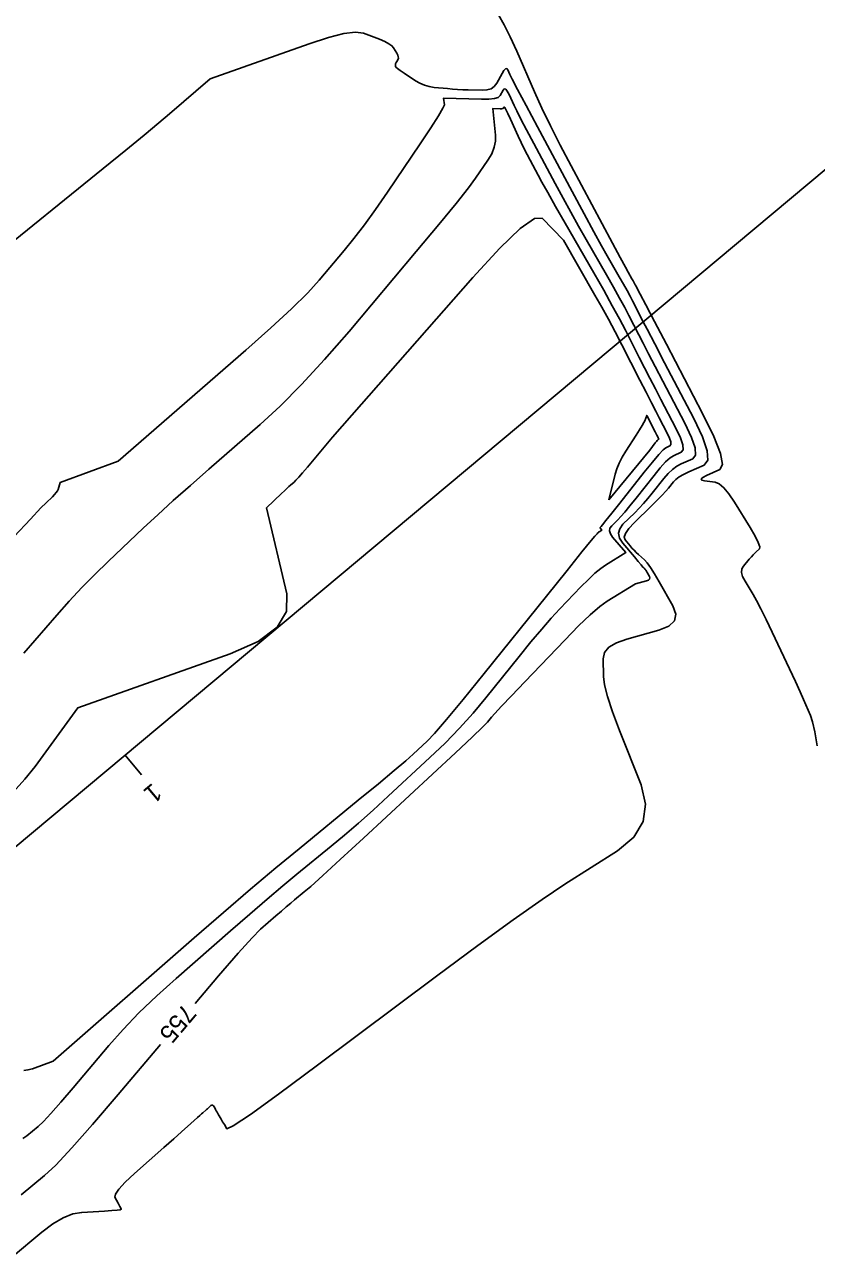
# Model space of a CAD drawing. Extents: x 2082232 to 2083549, y 592624 to 593832.
# Drawn here: x 2082789.01 to 2082819.92, y 593291.52 to 593339.64 of the extents above; entities that cross this region are included whole.
import ezdxf

# ---------------------------------------------------------------- set-up
doc = ezdxf.new("R2010")
doc.units = 0
for name, color, linetype in [('DT_X_Contour_Major', 7, 'Continuous'), ('DT_X_Contour_Minor', 7, 'Continuous'), ('GE_P_CL_5', 7, 'Continuous')]:
    doc.layers.add(name, color=color, linetype=linetype)

msp = doc.modelspace()

# ---------------------------------------------------------------- linework, layer by layer
at = {"layer": 'DT_X_Contour_Major'}
for points in [[(2082813.96, 593321.919), (2082814.129, 593322.115), (2082814.299, 593322.277), (2082814.468, 593322.404), (2082814.638, 593322.496), (2082815.089, 593322.696), (2082815.197, 593322.838), (2082815.182, 593323.117), (2082815.044, 593323.53), (2082814.782, 593324.08), (2082813.922, 593325.725), (2082813.621, 593326.301), (2082813.365, 593326.793), (2082813.154, 593327.201), (2082812.987, 593327.526), (2082812.602, 593328.282), (2082812.439, 593328.594), (2082812.238, 593328.964), (2082811.999, 593329.392), (2082811.722, 593329.878), (2082810.934, 593331.25), (2082810.636, 593331.773), (2082810.334, 593332.313), (2082810.028, 593332.87), (2082809.719, 593333.444), (2082808.887, 593334.997), (2082808.605, 593335.527), (2082808.383, 593335.952), (2082808.22, 593336.271), (2082808.117, 593336.485), (2082807.921, 593336.914), (2082807.851, 593337.046), (2082807.789, 593337.117), (2082807.735, 593337.127), (2082807.688, 593337.078), (2082807.572, 593336.867), (2082807.494, 593336.798), (2082807.348, 593336.752), (2082807.133, 593336.728), (2082806.85, 593336.726), (2082805.367, 593336.769), (2082805.395, 593336.512), (2082805.34, 593336.375), (2082805.165, 593336.075), (2082804.868, 593335.613), (2082804.45, 593334.987), (2082803.174, 593333.1), (2082802.71, 593332.427), (2082802.274, 593331.822), (2082801.866, 593331.285), (2082801.486, 593330.817), (2082800.512, 593329.66), (2082800.059, 593329.164), (2082799.43, 593328.545), (2082798.625, 593327.802), (2082797.645, 593326.935), (2082792.659, 593322.602), (2082790.395, 593321.764), (2082790.313, 593321.5), (2082790.287, 593321.439), (2082790.241, 593321.371), (2082790.176, 593321.295), (2082790.092, 593321.212), (2082789.843, 593320.979), (2082789.643, 593320.774), (2082789.23, 593320.332), (2082788.604, 593319.653)], [(2082795.662, 593301.437), (2082796.571, 593302.506), (2082797.339, 593303.39), (2082797.889, 593303.999), (2082798.222, 593304.332), (2082798.817, 593304.852), (2082799.03, 593305.038), (2082799.222, 593305.203), (2082799.395, 593305.349), (2082799.547, 593305.475), (2082799.926, 593305.785), (2082800.177, 593306.003), (2082800.645, 593306.427), (2082801.331, 593307.056), (2082802.234, 593307.891), (2082804.933, 593310.389), (2082805.827, 593311.218), (2082806.482, 593311.832), (2082806.899, 593312.23), (2082807.078, 593312.413), (2082807.239, 593312.613), (2082807.365, 593312.755), (2082807.623, 593313.031), (2082808.012, 593313.441), (2082808.532, 593313.985), (2082810.095, 593315.614), (2082810.637, 593316.167), (2082811.093, 593316.604), (2082811.463, 593316.925), (2082811.745, 593317.13), (2082812.863, 593317.815), (2082813.288, 593317.931), (2082813.363, 593317.96), (2082813.408, 593317.998), (2082813.421, 593318.043), (2082813.404, 593318.097), (2082813.316, 593318.252), (2082813.285, 593318.304), (2082813.259, 593318.345), (2082813.237, 593318.376), (2082813.22, 593318.394), (2082813.18, 593318.43), (2082813.146, 593318.467), (2082813.073, 593318.551), (2082812.962, 593318.682), (2082812.813, 593318.86), (2082812.362, 593319.397), (2082812.236, 593319.594), (2082812.195, 593319.783), (2082812.239, 593319.964), (2082812.368, 593320.137), (2082812.826, 593320.587), (2082812.997, 593320.761), (2082813.168, 593320.946), (2082813.339, 593321.143), (2082813.508, 593321.35), (2082813.96, 593321.919)], [(2082788.873, 593293.961), (2082789.786, 593294.718), (2082790.222, 593295.128), (2082790.847, 593295.793), (2082791.66, 593296.711), (2082792.662, 593297.882), (2082794.307, 593299.832)]]:
    msp.add_lwpolyline(points, dxfattribs=at)
at = {"layer": 'DT_X_Contour_Minor'}
for points in [[(2082807.513, 593340.023), (2082807.731, 593339.633), (2082807.966, 593339.16), (2082808.218, 593338.605), (2082808.914, 593337.012), (2082809.2, 593336.384), (2082809.533, 593335.693), (2082809.914, 593334.939), (2082810.344, 593334.123), (2082811.553, 593331.863), (2082811.957, 593331.11), (2082812.261, 593330.544), (2082812.465, 593330.167), (2082812.57, 593329.978), (2082812.716, 593329.723), (2082812.767, 593329.634), (2082812.811, 593329.554), (2082812.849, 593329.486), (2082812.879, 593329.428), (2082812.95, 593329.288), (2082813.04, 593329.116), (2082813.255, 593328.703), (2082813.596, 593328.052), (2082814.062, 593327.16), (2082815.473, 593324.463), (2082815.912, 593323.567), (2082816.17, 593322.903), (2082816.249, 593322.471), (2082816.146, 593322.27), (2082815.633, 593322.043), (2082815.484, 593321.966), (2082815.421, 593321.905), (2082815.445, 593321.861), (2082815.554, 593321.833), (2082815.962, 593321.779), (2082816.125, 593321.715), (2082816.306, 593321.564), (2082816.506, 593321.324), (2082816.724, 593320.997), (2082817.331, 593320.008), (2082817.525, 593319.677), (2082817.65, 593319.429), (2082817.706, 593319.262), (2082817.693, 593319.176), (2082817.568, 593319.057), (2082817.517, 593319.006), (2082817.455, 593318.94), (2082817.383, 593318.862), (2082817.301, 593318.769), (2082817.069, 593318.505), (2082817.007, 593318.394), (2082816.998, 593318.259), (2082817.039, 593318.099), (2082817.133, 593317.915), (2082817.45, 593317.393), (2082817.586, 593317.155), (2082817.755, 593316.83), (2082817.957, 593316.42), (2082818.193, 593315.925), (2082818.867, 593314.489), (2082819.097, 593313.998), (2082819.281, 593313.601), (2082819.419, 593313.3), (2082819.511, 593313.093), (2082819.695, 593312.667), (2082819.769, 593312.43), (2082819.854, 593312.037), (2082819.949, 593311.49)], [(2082787.595, 593330.408), (2082792.071, 593334.021), (2082792.952, 593334.735), (2082793.678, 593335.328), (2082794.25, 593335.802), (2082794.666, 593336.154), (2082796.245, 593337.519), (2082800.114, 593338.893), (2082800.869, 593339.14), (2082801.474, 593339.291), (2082801.93, 593339.345), (2082802.237, 593339.305), (2082802.856, 593339.068), (2082803.065, 593338.98), (2082803.227, 593338.895), (2082803.344, 593338.812), (2082803.413, 593338.732), (2082803.537, 593338.52), (2082803.575, 593338.447), (2082803.597, 593338.384), (2082803.601, 593338.332), (2082803.588, 593338.291), (2082803.533, 593338.197), (2082803.514, 593338.163), (2082803.5, 593338.132), (2082803.492, 593338.104), (2082803.488, 593338.079), (2082803.485, 593338.016), (2082803.505, 593337.981), (2082803.567, 593337.925), (2082803.672, 593337.846), (2082803.82, 593337.746), (2082804.269, 593337.449), (2082804.441, 593337.35), (2082804.619, 593337.273), (2082804.804, 593337.22), (2082804.996, 593337.19), (2082805.516, 593337.14), (2082805.712, 593337.123), (2082805.912, 593337.11), (2082806.114, 593337.099), (2082806.318, 593337.091), (2082806.868, 593337.076), (2082807.058, 593337.088), (2082807.216, 593337.138), (2082807.342, 593337.226), (2082807.437, 593337.35), (2082807.645, 593337.733), (2082807.718, 593337.849), (2082807.779, 593337.912), (2082807.829, 593337.921), (2082807.867, 593337.877), (2082807.953, 593337.687), (2082808.045, 593337.506), (2082808.255, 593337.106), (2082808.585, 593336.487), (2082809.033, 593335.648), (2082810.386, 593333.12), (2082810.852, 593332.252), (2082811.235, 593331.545), (2082811.535, 593330.999), (2082811.752, 593330.614), (2082812.219, 593329.801), (2082812.383, 593329.513), (2082812.525, 593329.259), (2082812.644, 593329.04), (2082812.741, 593328.855), (2082812.969, 593328.407), (2082813.097, 593328.158), (2082813.31, 593327.748), (2082813.608, 593327.176), (2082813.992, 593326.443), (2082815.128, 593324.271), (2082815.473, 593323.546), (2082815.655, 593323), (2082815.675, 593322.633), (2082815.533, 593322.445), (2082814.937, 593322.181), (2082814.732, 593322.083), (2082814.564, 593321.986), (2082814.433, 593321.89), (2082814.339, 593321.795), (2082814.139, 593321.543), (2082814.042, 593321.429), (2082813.9, 593321.277), (2082813.714, 593321.086), (2082813.484, 593320.857), (2082812.81, 593320.195), (2082812.598, 593319.967), (2082812.467, 593319.78), (2082812.418, 593319.632), (2082812.45, 593319.525), (2082812.645, 593319.293), (2082812.72, 593319.207), (2082812.799, 593319.122), (2082812.882, 593319.039), (2082812.97, 593318.958), (2082813.209, 593318.744), (2082813.312, 593318.63), (2082813.443, 593318.449), (2082813.6, 593318.2), (2082813.785, 593317.885), (2082814.314, 593316.954), (2082814.429, 593316.633), (2082814.377, 593316.366), (2082814.158, 593316.155), (2082813.772, 593316), (2082812.522, 593315.658), (2082812.112, 593315.513), (2082811.82, 593315.336), (2082811.647, 593315.126), (2082811.592, 593314.884), (2082811.602, 593314.194), (2082811.645, 593313.868), (2082811.765, 593313.408), (2082811.962, 593312.814), (2082812.237, 593312.087), (2082813.072, 593309.968), (2082813.25, 593309.211), (2082813.157, 593308.53), (2082812.792, 593307.925), (2082812.157, 593307.395), (2082810.102, 593306.083), (2082809.21, 593305.49), (2082808.076, 593304.695), (2082806.7, 593303.696), (2082805.082, 593302.496), (2082800.446, 593299.024), (2082798.92, 593297.892), (2082797.82, 593297.101), (2082797.146, 593296.651), (2082796.898, 593296.541), (2082796.804, 593296.703), (2082796.737, 593296.818), (2082796.706, 593296.871), (2082796.678, 593296.92), (2082796.604, 593297.048), (2082796.578, 593297.092), (2082796.538, 593297.162), (2082796.523, 593297.188), (2082796.489, 593297.247), (2082796.475, 593297.27), (2082796.46, 593297.295), (2082796.427, 593297.353), (2082796.379, 593297.436), (2082796.359, 593297.46), (2082796.337, 593297.469), (2082796.311, 593297.464), (2082796.282, 593297.445), (2082796.202, 593297.373), (2082796.171, 593297.346), (2082796.142, 593297.32), (2082796.113, 593297.294), (2082796.084, 593297.269), (2082795.97, 593297.168), (2082795.916, 593297.119), (2082795.843, 593297.055), (2082795.754, 593296.976), (2082795.491, 593296.743), (2082795.13, 593296.422), (2082794.826, 593296.152), (2082794.44, 593295.81), (2082793.3, 593294.799), (2082792.931, 593294.456), (2082792.681, 593294.187), (2082792.549, 593293.991), (2082792.535, 593293.868), (2082792.654, 593293.638), (2082792.694, 593293.561), (2082792.725, 593293.502), (2082792.758, 593293.437), (2082792.778, 593293.398), (2082792.743, 593293.383), (2082792.623, 593293.367), (2082792.417, 593293.35), (2082792.126, 593293.331), (2082791.236, 593293.279), (2082790.888, 593293.216), (2082790.513, 593293.066), (2082790.111, 593292.829), (2082789.681, 593292.505), (2082788.497, 593291.524)], [(2082813.581, 593322.044), (2082813.826, 593322.341), (2082814.034, 593322.568), (2082814.205, 593322.724), (2082814.339, 593322.81), (2082814.646, 593322.946), (2082814.719, 593323.043), (2082814.709, 593323.233), (2082814.615, 593323.514), (2082814.437, 593323.888), (2082813.851, 593325.008), (2082813.634, 593325.425), (2082813.42, 593325.837), (2082813.211, 593326.244), (2082813.006, 593326.646), (2082812.464, 593327.709), (2082812.234, 593328.149), (2082811.951, 593328.669), (2082811.615, 593329.271), (2082811.225, 593329.955), (2082810.116, 593331.886), (2082809.737, 593332.546), (2082809.433, 593333.08), (2082809.205, 593333.487), (2082809.051, 593333.768), (2082808.741, 593334.346), (2082808.625, 593334.568), (2082808.51, 593334.797), (2082808.395, 593335.036), (2082808.28, 593335.282), (2082807.975, 593335.952), (2082807.874, 593336.17), (2082807.799, 593336.321), (2082807.751, 593336.406), (2082807.73, 593336.424), (2082807.708, 593336.383), (2082807.693, 593336.37), (2082807.664, 593336.361), (2082807.623, 593336.356), (2082807.568, 593336.356), (2082807.283, 593336.364), (2082807.396, 593335.318), (2082807.395, 593335.089), (2082807.344, 593334.85), (2082807.242, 593334.601), (2082807.089, 593334.342), (2082806.613, 593333.64), (2082806.335, 593333.263), (2082805.855, 593332.661), (2082805.174, 593331.833), (2082804.292, 593330.779), (2082801.672, 593327.666), (2082800.718, 593326.564), (2082799.822, 593325.589), (2082798.984, 593324.744), (2082798.204, 593324.026), (2082796.199, 593322.285), (2082795.477, 593321.652), (2082794.811, 593321.059), (2082794.203, 593320.506), (2082793.653, 593319.993), (2082792.262, 593318.679), (2082791.746, 593318.179), (2082791.24, 593317.663), (2082790.744, 593317.131), (2082790.258, 593316.584), (2082788.977, 593315.104)], [(2082813.201, 593322.168), (2082813.522, 593322.566), (2082813.769, 593322.858), (2082813.941, 593323.044), (2082814.04, 593323.125), (2082814.203, 593323.197), (2082814.242, 593323.248), (2082814.236, 593323.349), (2082814.186, 593323.498), (2082814.092, 593323.696), (2082813.781, 593324.291), (2082813.646, 593324.55), (2082813.475, 593324.882), (2082813.268, 593325.287), (2082813.024, 593325.765), (2082812.326, 593327.136), (2082812.063, 593327.644), (2082811.801, 593328.137), (2082811.537, 593328.617), (2082811.274, 593329.084), (2082810.041, 593331.227), (2082809.214, 593332.08), (2082808.912, 593332.073), (2082808.36, 593331.686), (2082807.559, 593330.918), (2082806.509, 593329.771), (2082801.028, 593323.531), (2082800.05, 593322.37), (2082799.861, 593322.147), (2082799.71, 593321.974), (2082799.599, 593321.852), (2082799.527, 593321.782), (2082799.388, 593321.661), (2082799.327, 593321.606), (2082799.247, 593321.534), (2082799.149, 593321.443), (2082799.034, 593321.334), (2082798.451, 593320.783), (2082799.246, 593317.422), (2082799.235, 593316.736), (2082798.863, 593316.117), (2082798.13, 593315.565), (2082797.035, 593315.08), (2082791.08, 593312.976), (2082789.415, 593310.676), (2082789.021, 593310.182), (2082788.555, 593309.685)], [(2082811.82, 593321.086), (2082812.064, 593322.086), (2082812.128, 593322.303), (2082812.218, 593322.526), (2082812.334, 593322.753), (2082812.474, 593322.986), (2082812.883, 593323.613), (2082813.019, 593323.825), (2082813.121, 593323.989), (2082813.188, 593324.105), (2082813.221, 593324.174), (2082813.297, 593324.385), (2082813.62, 593323.75), (2082813.662, 593323.669), (2082813.692, 593323.61), (2082813.711, 593323.573), (2082813.747, 593323.505), (2082813.758, 593323.482), (2082813.763, 593323.465), (2082813.764, 593323.453), (2082813.759, 593323.447), (2082813.741, 593323.439), (2082813.729, 593323.429), (2082813.706, 593323.404), (2082813.674, 593323.366), (2082813.631, 593323.313), (2082813.41, 593323.033), (2082811.82, 593321.086)], [(2082788.933, 593296.16), (2082789.095, 593296.271), (2082789.53, 593296.631), (2082789.738, 593296.827), (2082790.036, 593297.143), (2082790.423, 593297.581), (2082790.9, 593298.139), (2082792.293, 593299.789), (2082792.848, 593300.417), (2082793.472, 593301.064), (2082794.164, 593301.729), (2082794.923, 593302.413), (2082797.038, 593304.262), (2082797.795, 593304.92), (2082798.48, 593305.508), (2082799.093, 593306.026), (2082799.634, 593306.474), (2082800.98, 593307.575), (2082801.498, 593308.006), (2082802.042, 593308.476), (2082802.611, 593308.982), (2082803.206, 593309.526), (2082804.828, 593311.027), (2082805.421, 593311.596), (2082805.983, 593312.174), (2082806.515, 593312.763), (2082807.016, 593313.363), (2082808.311, 593314.975), (2082808.774, 593315.545), (2082809.194, 593316.044), (2082809.569, 593316.472), (2082809.901, 593316.83), (2082810.726, 593317.69), (2082811.018, 593317.985), (2082811.275, 593318.226), (2082811.497, 593318.412), (2082811.684, 593318.543), (2082812.476, 593319.029), (2082811.964, 593319.639), (2082811.88, 593319.764), (2082811.845, 593319.879), (2082811.861, 593319.984), (2082811.927, 593320.078), (2082812.168, 593320.316), (2082812.281, 593320.435), (2082812.436, 593320.615), (2082812.635, 593320.856), (2082812.877, 593321.158), (2082813.581, 593322.044)], [(2082788.974, 593298.822), (2082789.138, 593298.839), (2082789.309, 593298.888), (2082790.124, 593299.183), (2082795.626, 593303.992), (2082796.766, 593304.983), (2082797.829, 593305.893), (2082798.813, 593306.723), (2082799.72, 593307.473), (2082802.034, 593309.365), (2082802.819, 593310.01), (2082803.438, 593310.524), (2082803.891, 593310.908), (2082804.178, 593311.162), (2082804.722, 593311.666), (2082805.015, 593311.973), (2082805.484, 593312.516), (2082806.13, 593313.296), (2082806.953, 593314.312), (2082809.382, 593317.337), (2082810.183, 593318.334), (2082810.765, 593319.056), (2082811.127, 593319.503), (2082811.27, 593319.674), (2082811.357, 593319.766), (2082811.388, 593319.797), (2082811.416, 593319.823), (2082811.439, 593319.842), (2082811.459, 593319.856), (2082811.543, 593319.908), (2082811.489, 593319.973), (2082811.48, 593319.986), (2082811.476, 593319.998), (2082811.478, 593320.01), (2082811.485, 593320.02), (2082811.511, 593320.045), (2082811.564, 593320.109), (2082811.704, 593320.285), (2082811.932, 593320.57), (2082812.246, 593320.966), (2082813.201, 593322.168)]]:
    msp.add_lwpolyline(points, dxfattribs=at)
at = {"layer": 'GE_P_CL_5'}
for p, q in [((2082825.425, 593338.296), (2082779.362, 593299.784)), ((2082792.926, 593311.124), (2082793.567, 593310.357))]:
    msp.add_line(p, q, dxfattribs=at)

# ---------------------------------------------------------------- texts
at = {"layer": 'DT_X_Contour_Major'}
msp.add_text('755', height=0.7, rotation=229.8301, dxfattribs=at).set_placement((2082795.227, 593301.465))
at = {"layer": 'GE_P_CL_5'}
msp.add_text('1', height=0.7, rotation=219.8982, dxfattribs=at).set_placement((2082793.999, 593310.067))

doc.saveas('drawing.dxf')
